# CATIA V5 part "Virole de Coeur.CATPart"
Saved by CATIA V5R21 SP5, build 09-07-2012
Part number: Virole de Coeur
Bounding box of the stored display mesh (mm): x -2371.34 to 2371.34, y -2368.892 to 2368.892, z -1160 to 1160
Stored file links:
  \\etu.ad.univ-lorraine.fr\bordron1\Documents\Parts EPR\Virole de Coeur.CATPart
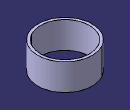
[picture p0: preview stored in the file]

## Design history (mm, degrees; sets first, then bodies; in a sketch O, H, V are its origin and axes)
AxisSystem1: origin (0, 0, 0), X (1, 0, 0), Y (0, 1, 0), Z (0, 0, 1)
Body1 (main body)
  Sketch1 on YZ plane of AxisSystem1, origin (0, 0, 0), H (0, 1, 0), V (0, 0, 1)
    line L1 (2140, 1160) -> (2372, 1160)
    line L2 (2372, 1160) -> (2372, -1160)
    line L3 (2372, -1160) -> (2140, -1160)
    line L4 (2140, -1160) -> (2140, 1160)
    reference projected line E1 through (0, 0) direction (0, 1) from edge [ZX plane of AxisSystem1 | YZ plane of AxisSystem1]
    reference projected line E2 through (0, 0) direction (1, 0) from edge [YZ plane of AxisSystem1 | XY plane of AxisSystem1]
    length L1 = 232
    length L2 = 2320
    distance E1 L4 = 2140
    horizontal: L1 H, L3 H
    vertical: L2 V, L4 V
    symmetry: L3 L1 E2
  Shaft1: profile Sketch1, axis edge [ZX plane of AxisSystem1 | YZ plane of AxisSystem1], angle 360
